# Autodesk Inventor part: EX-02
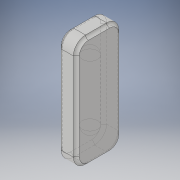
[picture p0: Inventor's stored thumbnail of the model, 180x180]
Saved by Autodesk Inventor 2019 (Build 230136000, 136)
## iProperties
Created: 2018-08
Part Number: EX-02
Material: Generic
Document SubType Name: Modeling
Designer: Power User
Density: 1 g/cm^3
Appearance: Default
Author: Power User
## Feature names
1. Extrusion1
2. Revolution1
3. Fillet1
4. Sweep1
5. Mirror1
## Parameters: d10 = 74 mm, d12 = 8 mm, d13 = 12 mm, d14 = 0, d16 = 5 mm, d19 = 90 deg, d20 = 4 mm, d21 = 0, d22 = 0, d23 = 2 mm
